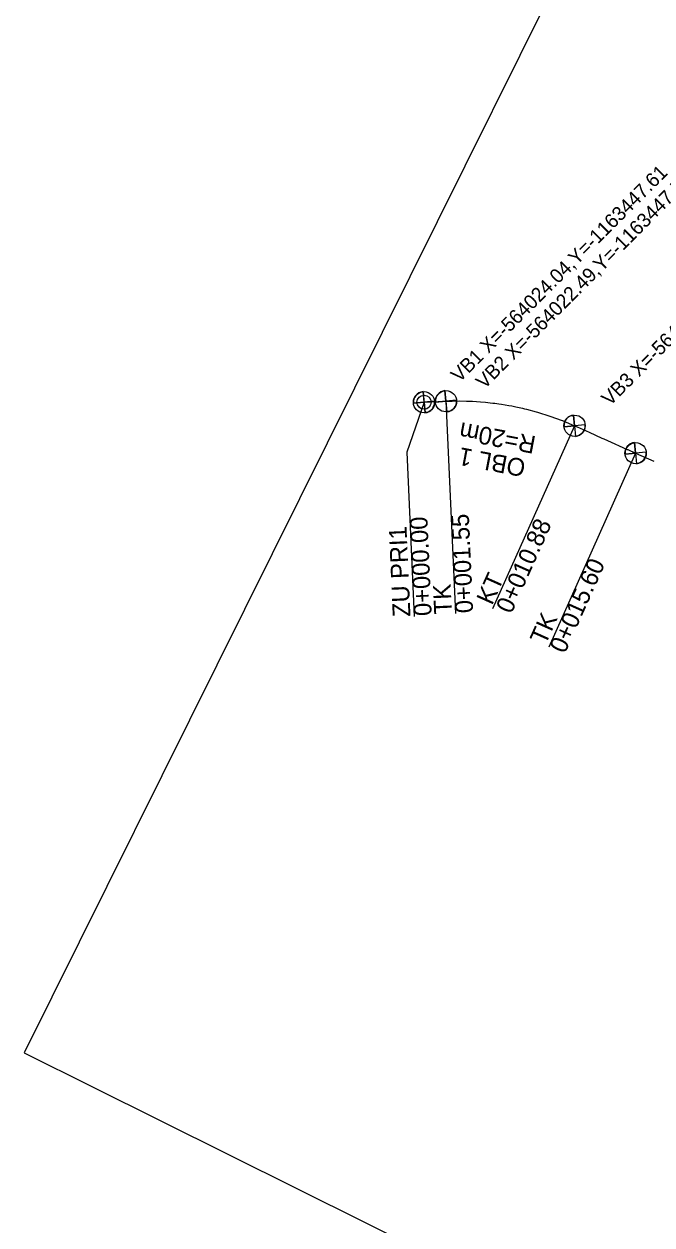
# Model space of a CAD drawing. Extents: x -564052 to -563798, y -1163587 to -1163361.
# Drawn here: x -564052.3 to -564007.9, y -1163505.7 to -1163420.9 of the extents above; entities that cross this region are included whole.
import ezdxf

# ---------------------------------------------------------------- set-up
doc = ezdxf.new("R2010")
doc.units = 0
for name, color, linetype in [('_popis staničení PRI1', 7, 'Continuous'), ('_rám C35', 7, 'Continuous'), ('_rám PH2 a PH4', 7, 'Continuous'), ('Default', 7, 'Continuous')]:
    doc.layers.add(name, color=color, linetype=linetype)

msp = doc.modelspace()

# ---------------------------------------------------------------- linework, layer by layer
msp.add_lwpolyline([(-564024.04, -1163447.61), (-564023.041, -1163447.565), (-564022.901, -1163447.559), (-564022.489, -1163447.54), (-564022.042, -1163447.525), (-564021.557, -1163447.52), (-564021.042, -1163447.528), (-564020.935, -1163447.531), (-564020.624, -1163447.544), (-564020.043, -1163447.58), (-564019.694, -1163447.611), (-564019.38, -1163447.643), (-564019.18, -1163447.666), (-564019.049, -1163447.683), (-564019.035, -1163447.685), (-564019.033, -1163447.685), (-564018.768, -1163447.721), (-564018.575, -1163447.749), (-564018.06, -1163447.835), (-564017.848, -1163447.874), (-564017.553, -1163447.932), (-564017.081, -1163448.036), (-564016.936, -1163448.07), (-564016.805, -1163448.102), (-564016.131, -1163448.28), (-564016.113, -1163448.286), (-564016.034, -1163448.308), (-564015.158, -1163448.584), (-564015.145, -1163448.588), (-564014.278, -1163448.906), (-564014.269, -1163448.909), (-564014.22, -1163448.929), (-564013.409, -1163449.271), (-564013.3, -1163449.32), (-564013.23, -1163449.352), (-564012.387, -1163449.729), (-564011.475, -1163450.139), (-564011.346, -1163450.196), (-564010.562, -1163450.548), (-564010.269, -1163450.68), (-564009.689, -1163450.94), (-564009.65, -1163450.957), (-564009.099, -1163451.204), (-564008.896, -1163451.295), (-564008.737, -1163451.365), (-564007.821, -1163451.766)])
at = {"layer": '_popis staničení PRI1'}
for points in [[(-564024.04, -1163447.61), (-564025.264, -1163451.137), (-564024.744, -1163462.722)], [(-564022.489, -1163447.54), (-564021.817, -1163462.525)], [(-564013.409, -1163449.271), (-564019.206, -1163462.198)], [(-564009.099, -1163451.204), (-564015.237, -1163464.891)]]:
    msp.add_lwpolyline(points, dxfattribs=at)
msp.add_circle((-564024.04, -1163447.61), 0.5, dxfattribs=at)
at = {"layer": '_rám C35'}
for p, q in [((-564024.04, -1163447.61), (-564024.11, -1163446.863)), ((-564024.04, -1163447.61), (-564024.11, -1163446.863)), ((-564024.109, -1163446.863), (-564023.971, -1163448.357)), ((-564022.489, -1163447.54), (-564022.559, -1163446.793)), ((-564022.489, -1163447.54), (-564022.559, -1163446.793)), ((-564022.559, -1163446.794), (-564022.42, -1163448.287)), ((-564023.293, -1163447.541), (-564024.787, -1163447.679)), ((-564024.787, -1163447.68), (-564024.04, -1163447.61)), ((-564024.787, -1163447.679), (-564024.04, -1163447.61)), ((-564023.293, -1163447.54), (-564024.04, -1163447.61)), ((-564024.04, -1163447.61), (-564023.97, -1163448.357)), ((-564021.743, -1163447.471), (-564023.236, -1163447.61)), ((-564023.236, -1163447.61), (-564022.489, -1163447.54)), ((-564023.236, -1163447.61), (-564022.489, -1163447.54)), ((-564021.742, -1163447.471), (-564022.489, -1163447.54)), ((-564022.489, -1163447.54), (-564022.42, -1163448.288)), ((-564013.479, -1163448.524), (-564013.34, -1163450.018)), ((-564013.409, -1163449.271), (-564013.479, -1163448.524)), ((-564013.409, -1163449.271), (-564013.479, -1163448.524)), ((-564012.663, -1163449.202), (-564014.156, -1163449.341)), ((-564014.156, -1163449.341), (-564013.409, -1163449.271)), ((-564014.156, -1163449.341), (-564013.409, -1163449.271)), ((-564012.662, -1163449.202), (-564013.409, -1163449.271)), ((-564013.409, -1163449.271), (-564013.34, -1163450.018)), ((-564008.353, -1163451.134), (-564009.846, -1163451.273)), ((-564009.169, -1163450.457), (-564009.03, -1163451.95)), ((-564009.099, -1163451.204), (-564009.169, -1163450.457)), ((-564009.099, -1163451.204), (-564009.169, -1163450.457)), ((-564008.352, -1163451.134), (-564009.099, -1163451.204)), ((-564009.847, -1163451.273), (-564009.099, -1163451.204)), ((-564009.847, -1163451.273), (-564009.099, -1163451.204)), ((-564009.099, -1163451.204), (-564009.03, -1163451.951))]:
    msp.add_line(p, q, dxfattribs=at)
for centre in [(-564024.04, -1163447.61), (-564022.489, -1163447.54), (-564013.409, -1163449.271), (-564009.099, -1163451.204)]:
    msp.add_circle(centre, 0.75, dxfattribs=at)
for centre, start, end in [((-564024.04, -1163447.61), 95.31679, 185.31679), ((-564024.04, -1163447.61), 95.31679, 185.31679), ((-564022.489, -1163447.54), 95.31679, 185.31679), ((-564022.489, -1163447.54), 95.31679, 185.31679), ((-564024.04, -1163447.61), 275.31679, 5.31679), ((-564022.489, -1163447.54), 275.31679, 5.31679), ((-564013.409, -1163449.271), 95.31679, 185.31679), ((-564013.409, -1163449.271), 95.31679, 185.31679), ((-564013.409, -1163449.271), 275.31679, 5.31679), ((-564009.099, -1163451.204), 95.31679, 185.31679), ((-564009.099, -1163451.204), 95.31679, 185.31679), ((-564009.099, -1163451.204), 275.31679, 5.31679)]:
    msp.add_arc(centre, 0.75, start, end, dxfattribs=at)
at = {"layer": '_rám PH2 a PH4'}
msp.add_lwpolyline([(-564052.283, -1163493.529), (-563864.244, -1163587.024), (-563798.13, -1163454.054), (-563986.169, -1163360.559)], close=True, dxfattribs=at)

# ---------------------------------------------------------------- texts
at = {"layer": '_popis staničení PRI1'}
for s, rotation, p in [('R=20m ', 169.20833, (-564016.073, -1163450.029)), ('OBL 1', 169.20833, (-564016.793, -1163451.673)), ('0+000.00', 92.56938, (-564023.495, -1163462.666)), ('0+001.55', 92.56938, (-564020.568, -1163462.469)), ('0+010.88', 65.84728, (-564017.873, -1163462.598)), ('ZU PRI1', 92.56938, (-564024.994, -1163462.733)), ('0+015.60', 65.84728, (-564014.096, -1163465.402)), ('KT ', 65.84728, (-564019.241, -1163461.985)), ('TK ', 92.56938, (-564022.067, -1163462.537)), ('TK ', 65.84728, (-564015.465, -1163464.788))]:
    msp.add_text(s, height=1.25, rotation=rotation, dxfattribs=at).set_placement(p)
at = {"layer": 'Default'}
for s, p in [('VB1 X=-564024.04,Y=-1163447.61', (-564021.54, -1163446.262)), ('VB2 X=-564022.49,Y=-1163447.54', (-564019.779, -1163446.729)), ('VB3 X=-564013.41,Y=-1163449.27', (-564010.91, -1163447.923))]:
    msp.add_text(s, height=1, rotation=45, dxfattribs=at).set_placement(p)

doc.saveas('drawing.dxf')
